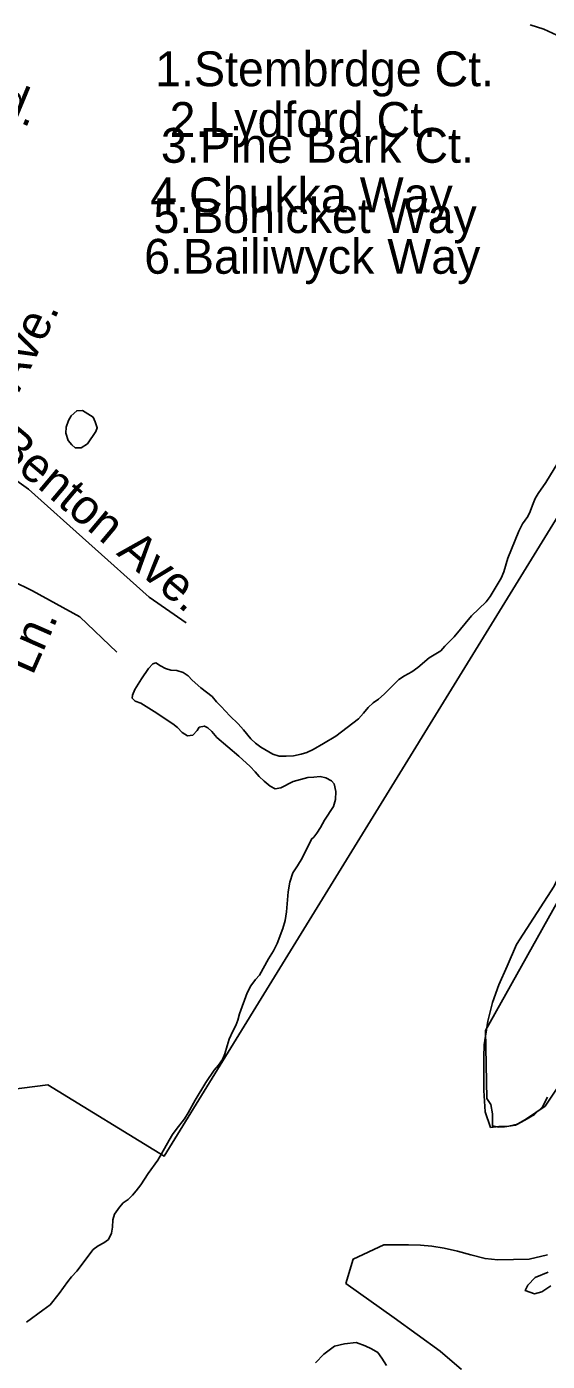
# Model space of a CAD drawing. Extents: x 2290055 to 2389491, y 66597 to 237875.
# Drawn here: x 2346740 to 2348162, y 150018 to 153657 of the extents above; entities that cross this region are included whole.
import ezdxf

# ---------------------------------------------------------------- set-up
doc = ezdxf.new("R2010")
doc.units = 0
for name, color, linetype in [('Exist Boundary Political City Limit New', 7, 'Continuous'), ('Exist Hydrographic Creek Single Shore', 7, 'Continuous'), ('Exist Hydrographic Island Shore', 7, 'Continuous'), ('Exist Hydrographic Pond Under 1500 Sq Ft', 7, 'Continuous'), ('Exist Hydrographic River Shore', 7, 'Continuous'), ('Exist Road Non-System Type 51', 7, 'Continuous'), ('Exist Road Non-System Type 51 Label', 7, 'Continuous'), ('Map Preparation Boundary City Limit Buffer Line', 7, 'Continuous')]:
    doc.layers.add(name, color=color, linetype=linetype)

msp = doc.modelspace()

# ---------------------------------------------------------------- linework, layer by layer
at = {"layer": 'Exist Boundary Political City Limit New'}
msp.add_lwpolyline([(2349898.5, 155096.5), (2347115.8, 150577.3), (2346798.2, 150771.2), (2346691.2, 150757.8), (2346571, 150677.6), (2346303.8, 150741.1), (2346043.2, 150687.6), (2345846, 150737.8), (2345622.2, 150764.5), (2345445.2, 151015.2), (2345298.2, 151031.9), (2345137.8, 151219.1), (2345174.5, 151449.7), (2345007.5, 151265.9), (2344880.5, 151272.6), (2344747, 151456.4), (2344556.5, 151456.4), (2344473, 151406.3), (2344296, 151402.9), (2344042, 151249.2), (2343734.8, 151296)], dxfattribs=at)
at = {"layer": 'Exist Hydrographic Creek Single Shore'}
for points in [[(2347988.7, 150847.3), (2347989.1, 150881), (2347999.3, 150945), (2348012, 150995.8), (2348029.7, 151044.2), (2348052.2, 151095.1), (2348077.4, 151154.4), (2348180, 151313.1), (2348193.7, 151342)], [(2348162.5, 150738.2), (2348148.6, 150711.7), (2348126.5, 150690.4), (2348100, 150675.4), (2348080.5, 150664.4), (2348056.3, 150659.1), (2348028.9, 150657.6), (2348006.7, 150655.5), (2347991.9, 150698.2), (2347988.5, 150756), (2347988.7, 150847.3)], [(2347714.9, 150335.1), (2347631.4, 150296.2), (2347612, 150230), (2347743.2, 150136.1), (2347869.5, 150044.9), (2347927.3, 149995.5)], [(2348161.9, 150307.8), (2348112.1, 150296.4), (2348026.8, 150294.5), (2347991.9, 150297.9), (2347952.8, 150307.7), (2347916.5, 150318.2), (2347879.8, 150326.1), (2347846.1, 150331.7), (2347815.6, 150334.1), (2347782.6, 150334.8), (2347757, 150335.2), (2347733.8, 150334.9), (2347714.9, 150335.1)], [(2348171, 150223.3), (2348146.6, 150207.2), (2348126.5, 150201.7), (2348101.2, 150210.4), (2348106, 150219.8), (2348108.8, 150225.1), (2348128.7, 150246.1), (2348163.8, 150261.1)], [(2347580.2, 150058.8), (2347551.5, 150037.3), (2347528.5, 150013.5)], [(2347722.5, 150006.4), (2347709.6, 150026.5), (2347698.7, 150041.5), (2347681.3, 150052), (2347664.5, 150059.9), (2347639.5, 150068.7), (2347607.7, 150065.2), (2347580.2, 150058.8)]]:
    msp.add_lwpolyline(points, dxfattribs=at)
at = {"layer": 'Exist Hydrographic Island Shore'}
for points in [[(2347996.5, 150734.7), (2347992.8, 150920.1), (2348219.2, 151324.1), (2348274.8, 151401.6), (2348306.6, 151391.6), (2348384.1, 151379.7), (2348417.8, 151355.9), (2348475.4, 151334), (2348494.8, 151218.6), (2348467.9, 151111), (2348400.7, 151057.3), (2348346.9, 150990.1), (2348279.7, 150896), (2348221.2, 150811.8), (2348155.7, 150713.4)], [(2348155.7, 150713.4), (2348102, 150676.6), (2348075.2, 150661.7), (2348044.4, 150656.7), (2348029.5, 150655.7), (2348011.7, 150659.7), (2348011.7, 150692.5), (2348007.7, 150718.3), (2347996.5, 150734.7)]]:
    msp.add_lwpolyline(points, dxfattribs=at)
at = {"layer": 'Exist Hydrographic Pond Under 1500 Sq Ft'}
msp.add_lwpolyline([(2346889, 152509.3), (2346906.7, 152520.2), (2346929, 152553), (2346933.2, 152563.4), (2346932, 152565.8), (2346927.7, 152579.9), (2346921.5, 152592.9), (2346892.5, 152610.7), (2346877, 152609.9), (2346862.2, 152596.3), (2346854.2, 152583.5), (2346847.7, 152565), (2346847.5, 152548.5), (2346853.7, 152529.2), (2346863.2, 152517.1), (2346873, 152509.3), (2346889, 152509.3)], dxfattribs=at)
at = {"layer": 'Exist Hydrographic River Shore'}
for points in [[(2348114.5, 153662.3), (2348152, 153650.4), (2348187.5, 153634.8)], [(2348190.7, 152467.9), (2348157.2, 152414.4), (2348136.7, 152384.6), (2348128.7, 152370.4), (2348121, 152352.5), (2348114.7, 152335.4), (2348108, 152321.3), (2348093.7, 152301.5), (2348083.5, 152281.5), (2348053.7, 152207.7), (2348043.2, 152170.8), (2348035.5, 152153.3), (2348005.7, 152103), (2347994.7, 152088.6), (2347954.5, 152050.5), (2347907, 151993.4), (2347881.5, 151968.2), (2347870.7, 151954.8), (2347839.5, 151936.2), (2347807.7, 151909.7), (2347791.7, 151898.4), (2347772, 151887.5), (2347756.7, 151877), (2347744, 151865.5), (2347716.5, 151837.4), (2347701.2, 151823.8), (2347686.5, 151813.4), (2347672.5, 151800.7), (2347660.2, 151785.3), (2347646, 151769.9), (2347584, 151722.5)], [(2347584, 151722.5), (2347551, 151702.6), (2347522, 151686.3), (2347505.2, 151677.9), (2347489.7, 151673.1), (2347469, 151669.2), (2347449, 151667.6), (2347429.5, 151668.2), (2347412, 151673.5), (2347379.2, 151692.4), (2347364.7, 151703), (2347352.7, 151715), (2347332.2, 151739.9), (2347317.7, 151755.8), (2347295.2, 151777.7), (2347271.7, 151803), (2347258.2, 151816.1), (2347246.5, 151831), (2347215.5, 151854.2), (2347192.5, 151875.5), (2347181.5, 151887.5), (2347167.2, 151896.4), (2347150.2, 151901.2), (2347134.2, 151902.3), (2347119, 151907.2), (2347105.5, 151914), (2347093, 151922.1), (2347084.7, 151920), (2347073, 151906.7), (2347054, 151878.5), (2347036, 151849.7), (2347029, 151834.6), (2347028, 151826.2), (2347036.2, 151817.8), (2347052, 151812.1), (2347095.2, 151785.6), (2347110, 151774.9), (2347139.2, 151756.1), (2347152.2, 151746.2), (2347165, 151732.5), (2347179.5, 151723.8), (2347193.5, 151725.6), (2347206.2, 151737.8), (2347211.5, 151746.6), (2347225.5, 151749.9), (2347234.5, 151745.6), (2347245.5, 151735), (2347259, 151719.2), (2347319.7, 151667.9), (2347350.2, 151639.9), (2347364, 151625.6), (2347375, 151612.5), (2347388.5, 151599.7), (2347405, 151586.5), (2347418.7, 151579.3), (2347433.7, 151581.2), (2347468, 151599.3), (2347507.5, 151609.8), (2347524.5, 151610.8), (2347541.5, 151612.8), (2347556.7, 151608.6), (2347572.5, 151601), (2347580, 151592.3), (2347584, 151571.3), (2347583.2, 151549.8), (2347577.5, 151531), (2347553.5, 151493), (2347542.2, 151473), (2347532.7, 151458.3), (2347524, 151447.4), (2347518.2, 151441.6), (2347492.5, 151389.5), (2347480, 151369), (2347467, 151349.9), (2347458.5, 151324.4), (2347454, 151298.1), (2347449.2, 151243.1), (2347446, 151219.4), (2347439.7, 151197.9), (2347424, 151157.1), (2347413.7, 151136.6), (2347400.5, 151114.8), (2347375.5, 151070.6), (2347365, 151059), (2347352.7, 151042), (2347342.5, 151022.7), (2347321, 150965.4), (2347316.5, 150948.3), (2347311, 150933.3), (2347302.7, 150917.5), (2347293.5, 150896.2), (2347287.5, 150878.3), (2347281.5, 150856.5), (2347274.5, 150840.6), (2347263.7, 150825.4), (2347252.2, 150811.2), (2347229.5, 150778.2), (2347200, 150730.2), (2347181.5, 150694.9), (2347171, 150679.3)], [(2347171, 150679.3), (2347148, 150650.2), (2347138.2, 150636.1), (2347129, 150620.7), (2347108.7, 150583.1), (2347098, 150565.7), (2347072, 150529.4), (2347051.7, 150498.5), (2347039.5, 150482.4), (2347029, 150470.7), (2347017.5, 150459.2), (2347003.5, 150449.6), (2346993.5, 150437.6), (2346980.2, 150418.6), (2346975.5, 150403.6), (2346974.7, 150383.8), (2346972.2, 150366.7), (2346963.5, 150349.5), (2346951, 150340.8), (2346935.5, 150332.4), (2346921.7, 150322.3), (2346877.7, 150263.6), (2346863, 150247.7), (2346852.7, 150234.8), (2346829, 150202.1), (2346804.2, 150171.9), (2346784.7, 150156.6), (2346740, 150124.2)]]:
    msp.add_lwpolyline(points, dxfattribs=at)
at = {"layer": 'Exist Road Non-System Type 51'}
for points in [[(2346549.3, 152638.2), (2346548, 152564.7), (2346594.1, 152503.2), (2346745.4, 152395.7)], [(2346147.3, 152428.4), (2346251.9, 152377.7), (2346572.2, 152215.2), (2346644.5, 152173.5), (2346756.4, 152118.6), (2346885.8, 152048.4), (2346986.7, 151951.8)], [(2346745.4, 152395.7), (2347074.5, 152101.5), (2347175.4, 152031.3)]]:
    msp.add_lwpolyline(points, dxfattribs=at)
at = {"layer": 'Map Preparation Boundary City Limit Buffer Line'}
msp.add_lwpolyline([(2349898.5, 155096.5), (2347115.8, 150577.3), (2346798.2, 150771.2), (2346691.2, 150757.8), (2346571, 150677.6), (2346303.8, 150741.1), (2346043.2, 150687.6), (2345846, 150737.8), (2345622.2, 150764.5), (2345445.2, 151015.2), (2345298.2, 151031.9), (2345137.8, 151219.1), (2345174.5, 151449.7), (2345007.5, 151265.9), (2344880.5, 151272.6), (2344747, 151456.4), (2344556.5, 151456.4), (2344473, 151406.3), (2344296, 151402.9), (2344042, 151249.2), (2343734.8, 151296)], dxfattribs=at)

# ---------------------------------------------------------------- texts
at = {"layer": 'Exist Road Non-System Type 51 Label'}
for s, p in [('1.Stembrdge Ct.', (2347091.2, 153495.1)), ('2.Lydford Ct.', (2347130.4, 153356.9)), ('3.Pine Bark Ct.', (2347106.8, 153286.3)), ('4.Chukka Way', (2347077.6, 153151.3)), ('5.Bohicket Way', (2347086.4, 153094.7)), ('6.Bailiwyck Way', (2347061.1, 152983.7))]:
    msp.add_text(s, height=95, dxfattribs=at).set_placement(p)
for s, rotation, p in [('Rd.', 337.4345, (2346569.9, 153458.6)), ('2nd Ave.', 63.9047, (2346610.8, 152437.7)), ('Benton Ave.', 319.8556, (2346648.2, 152501.6)), ('Ln.', 66.2403, (2346756.4, 151885.9))]:
    msp.add_text(s, height=95, rotation=rotation, dxfattribs=at).set_placement(p)

doc.saveas('drawing.dxf')
